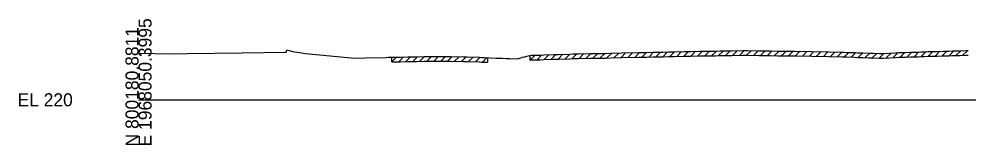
# Model space of a CAD drawing. Extents: x -119 to 6018, y -82 to 34226.
# Drawn here: x -25.7 to 178.2, y 31988.3 to 32015.3 of the extents above; entities that cross this region are included whole.
import ezdxf

# ---------------------------------------------------------------- set-up
doc = ezdxf.new("R2010")
doc.units = 0
for name, color, linetype in [('Default', 7, 'Continuous'), ('RD_GPK_XS_Cell', 7, 'Continuous'), ('RD_XS_ExGround', 7, 'Continuous'), ('RD_XS_ExPaveRet', 7, 'Continuous')]:
    doc.layers.add(name, color=color, linetype=linetype)

msp = doc.modelspace()

# ---------------------------------------------------------------- linework, layer by layer
at = {"layer": 'RD_GPK_XS_Cell'}
msp.add_line((0, 31998), (300, 31998), dxfattribs=at)
at = {"layer": 'RD_XS_ExGround'}
msp.add_lwpolyline([(0, 32008), (6.95, 32007.87), (10.52, 32007.91), (22.19, 32008.08), (31.74, 32008.2), (31.84, 32008.7), (33.05, 32008.33), (33.59, 32008.26), (34.15, 32008.21), (35.86, 32007.91), (38.17, 32007.7), (46.41, 32006.91), (48.78, 32007), (53.2, 32007.09), (53.66, 32007.11), (54.9, 32007.15), (55.85, 32007.16), (56.24, 32007.17), (57.83, 32007.2), (59.76, 32007.24), (61.35, 32007.26), (63.35, 32007.29), (65.85, 32007.32), (66.55, 32007.31), (67.02, 32007.3), (69.83, 32007.21), (70.58, 32007.19), (73.21, 32007.11), (73.69, 32007.1), (74.26, 32007.07), (75.53, 32007.01), (76.85, 32006.96), (77.22, 32006.95), (77.79, 32006.92), (78.19, 32006.91), (79, 32006.87), (79.79, 32006.85), (81.4, 32006.82), (82.11, 32007), (82.53, 32007.11), (82.98, 32007.22), (83.41, 32007.33), (84.33, 32007.55), (85.6, 32007.59), (86.38, 32007.6), (87.12, 32007.63), (89.13, 32007.71), (89.68, 32007.73), (90.22, 32007.74), (92.68, 32007.82), (93.4, 32007.84), (94.53, 32007.89), (97, 32007.93), (100.35, 32007.96), (101.41, 32007.99), (103.85, 32008.04), (107.44, 32008.11), (109.16, 32008.16), (110.53, 32008.19), (111.35, 32008.21), (112.63, 32008.24), (113.89, 32008.27), (115.08, 32008.3), (117.29, 32008.36), (117.98, 32008.38), (118.64, 32008.39), (120.64, 32008.42), (121.44, 32008.43), (122.36, 32008.44), (123.24, 32008.45), (124, 32008.46), (124.98, 32008.47), (126.14, 32008.49), (126.87, 32008.5), (127.45, 32008.51), (129.87, 32008.54), (130.86, 32008.54), (133.39, 32008.5), (134.26, 32008.49), (135.69, 32008.48), (137.33, 32008.46), (137.73, 32008.46), (139.17, 32008.45), (141.11, 32008.42), (144.68, 32008.35), (148.28, 32008.26), (151.15, 32008.2), (151.52, 32008.19), (152.14, 32008.18), (153.82, 32008.14), (154.55, 32008.1), (155.65, 32008.06), (156.91, 32008.02), (157.96, 32007.99), (159.25, 32007.94), (160.07, 32007.94), (162.66, 32008.08), (163.35, 32008.13), (164.06, 32008.14), (164.81, 32008.16), (165.87, 32008.2), (166.37, 32008.22), (167.05, 32008.24), (167.51, 32008.25), (168.17, 32008.28), (168.76, 32008.3), (169.58, 32008.33), (170.24, 32008.34), (171.55, 32008.38), (172.9, 32008.42), (174.12, 32008.45), (174.92, 32008.48), (176.42, 32008.52), (177.76, 32008.56), (178.3, 32008.57)], dxfattribs=at)
at = {"layer": 'RD_XS_ExPaveRet'}
for p, q in [((177.15, 32007.54), (178.17, 32008.57)), ((54.42, 32006.14), (55.44, 32007.16)), ((54.42, 32006.14), (54.42, 32007.14)), ((55.92, 32006.16), (56.94, 32007.18)), ((57.42, 32006.19), (58.44, 32007.21)), ((58.92, 32006.22), (59.94, 32007.24)), ((60.42, 32006.25), (61.44, 32007.27)), ((61.92, 32006.27), (62.93, 32007.29)), ((63.42, 32006.29), (64.43, 32007.3)), ((64.92, 32006.31), (65.93, 32007.32)), ((66.42, 32006.31), (67.39, 32007.29)), ((67.92, 32006.27), (68.89, 32007.24)), ((69.42, 32006.22), (70.39, 32007.19)), ((70.92, 32006.18), (71.89, 32007.15)), ((72.42, 32006.13), (73.39, 32007.11)), ((73.92, 32006.08), (74.87, 32007.04)), ((74.95, 32007.04), (74.95, 32006.04)), ((84.15, 32006.51), (85.21, 32007.58)), ((84.15, 32006.51), (84.15, 32007.51)), ((84.15, 32006.51), (84.33, 32006.55)), ((84.33, 32006.55), (85.6, 32006.59)), ((85.6, 32006.59), (86.38, 32006.6)), ((85.65, 32006.59), (86.67, 32007.61)), ((86.38, 32006.6), (87.12, 32006.63)), ((87.12, 32006.63), (89.13, 32006.71)), ((87.15, 32006.63), (88.19, 32007.67)), ((88.65, 32006.69), (89.68, 32007.73)), ((89.13, 32006.71), (89.68, 32006.73)), ((89.68, 32006.73), (90.22, 32006.74)), ((90.15, 32006.74), (91.18, 32007.77)), ((90.22, 32006.74), (92.68, 32006.82)), ((91.65, 32006.79), (92.68, 32007.82)), ((92.68, 32006.82), (93.4, 32006.84)), ((93.15, 32006.83), (94.19, 32007.87)), ((93.4, 32006.84), (94.53, 32006.89)), ((94.53, 32006.89), (97, 32006.93)), ((94.65, 32006.89), (95.67, 32007.91)), ((96.15, 32006.92), (97.17, 32007.94)), ((97, 32006.93), (100.35, 32006.96)), ((97.65, 32006.94), (98.66, 32007.95)), ((99.15, 32006.95), (100.16, 32007.96)), ((100.35, 32006.96), (101.41, 32006.99)), ((100.65, 32006.97), (101.67, 32007.99)), ((101.41, 32006.99), (103.85, 32007.04)), ((102.15, 32007), (103.17, 32008.02)), ((103.65, 32007.03), (104.67, 32008.05)), ((103.85, 32007.04), (107.44, 32007.11)), ((105.15, 32007.06), (106.17, 32008.09)), ((106.65, 32007.1), (107.67, 32008.12)), ((107.44, 32007.11), (109.16, 32007.16)), ((108.15, 32007.13), (109.17, 32008.16)), ((109.16, 32007.16), (110.53, 32007.19)), ((109.65, 32007.17), (110.67, 32008.19)), ((110.53, 32007.19), (111.35, 32007.21)), ((111.15, 32007.21), (112.17, 32008.23)), ((111.35, 32007.21), (112.63, 32007.24)), ((112.63, 32007.24), (113.89, 32007.27)), ((112.65, 32007.24), (113.67, 32008.27)), ((113.89, 32007.27), (115.08, 32007.3)), ((114.15, 32007.28), (115.17, 32008.31)), ((115.08, 32007.3), (117.29, 32007.36)), ((115.65, 32007.32), (116.68, 32008.35)), ((117.15, 32007.36), (118.17, 32008.39)), ((117.29, 32007.36), (117.98, 32007.38)), ((117.98, 32007.38), (118.64, 32007.39)), ((118.64, 32007.39), (120.64, 32007.42)), ((118.65, 32007.39), (119.66, 32008.41)), ((120.15, 32007.41), (121.16, 32008.43)), ((120.64, 32007.42), (121.44, 32007.43)), ((121.44, 32007.43), (122.36, 32007.44)), ((121.65, 32007.43), (122.66, 32008.45)), ((122.36, 32007.44), (123.24, 32007.45)), ((123.15, 32007.45), (124.16, 32008.46)), ((123.24, 32007.45), (124, 32007.46)), ((124, 32007.46), (124.98, 32007.47)), ((124.65, 32007.47), (125.66, 32008.48)), ((124.98, 32007.47), (126.14, 32007.49)), ((126.14, 32007.49), (126.87, 32007.5)), ((126.15, 32007.49), (127.16, 32008.51)), ((126.87, 32007.5), (127.45, 32007.51)), ((127.45, 32007.51), (129.87, 32007.54)), ((127.65, 32007.51), (128.66, 32008.53)), ((129.15, 32007.53), (130.15, 32008.54)), ((129.87, 32007.54), (130.86, 32007.54)), ((130.65, 32007.54), (131.64, 32008.53)), ((130.86, 32007.54), (133.39, 32007.5)), ((132.15, 32007.52), (133.13, 32008.51)), ((133.39, 32007.5), (134.26, 32007.49)), ((133.65, 32007.5), (134.64, 32008.49)), ((134.26, 32007.49), (135.69, 32007.48)), ((135.15, 32007.48), (136.14, 32008.47)), ((135.69, 32007.48), (137.33, 32007.46)), ((136.65, 32007.47), (137.64, 32008.46)), ((137.33, 32007.46), (137.73, 32007.46)), ((137.73, 32007.46), (139.17, 32007.45)), ((138.15, 32007.45), (139.14, 32008.45)), ((139.17, 32007.45), (141.11, 32007.42)), ((139.65, 32007.44), (140.64, 32008.43)), ((141.11, 32007.42), (144.68, 32007.35)), ((141.15, 32007.42), (142.13, 32008.4)), ((142.65, 32007.39), (143.63, 32008.37)), ((144.15, 32007.36), (145.13, 32008.34)), ((144.68, 32007.35), (148.28, 32007.26)), ((145.65, 32007.33), (146.62, 32008.3)), ((147.15, 32007.29), (148.12, 32008.27)), ((148.28, 32007.26), (151.15, 32007.2)), ((148.65, 32007.26), (149.63, 32008.23)), ((150.15, 32007.22), (151.13, 32008.2)), ((151.15, 32007.2), (151.52, 32007.19)), ((151.52, 32007.19), (152.14, 32007.18)), ((151.65, 32007.19), (152.63, 32008.17)), ((152.14, 32007.18), (153.82, 32007.14)), ((153.15, 32007.16), (154.12, 32008.13)), ((153.82, 32007.14), (154.55, 32007.1)), ((154.55, 32007.1), (155.65, 32007.06)), ((154.65, 32007.1), (155.61, 32008.06)), ((155.65, 32007.06), (156.91, 32007.02)), ((156.15, 32007.05), (157.12, 32008.02)), ((156.91, 32007.02), (157.96, 32006.99)), ((157.65, 32007), (158.61, 32007.96)), ((157.96, 32006.99), (159.25, 32006.94)), ((159.15, 32006.95), (160.14, 32007.94)), ((159.25, 32006.94), (160.07, 32006.94)), ((160.07, 32006.94), (162.66, 32007.08)), ((160.65, 32006.97), (161.71, 32008.03)), ((162.15, 32007.05), (163.21, 32008.12)), ((162.66, 32007.08), (163.35, 32007.13)), ((163.35, 32007.13), (164.06, 32007.14)), ((163.65, 32007.13), (164.67, 32008.16)), ((164.06, 32007.14), (164.81, 32007.16)), ((164.81, 32007.16), (165.87, 32007.2)), ((165.15, 32007.18), (166.19, 32008.21)), ((165.87, 32007.2), (166.37, 32007.22)), ((166.37, 32007.22), (167.05, 32007.24)), ((166.65, 32007.23), (167.68, 32008.26)), ((167.05, 32007.24), (167.51, 32007.25)), ((167.51, 32007.25), (168.17, 32007.28)), ((168.15, 32007.28), (169.18, 32008.31)), ((168.17, 32007.28), (168.76, 32007.3)), ((168.76, 32007.3), (169.58, 32007.33)), ((169.58, 32007.33), (170.24, 32007.34)), ((169.65, 32007.33), (170.68, 32008.36)), ((170.24, 32007.34), (171.55, 32007.38)), ((171.15, 32007.37), (172.18, 32008.4)), ((171.55, 32007.38), (172.9, 32007.42)), ((172.65, 32007.41), (173.68, 32008.44)), ((172.9, 32007.42), (174.12, 32007.45)), ((174.12, 32007.45), (174.92, 32007.48)), ((174.15, 32007.45), (175.18, 32008.48)), ((174.92, 32007.48), (176.42, 32007.52)), ((175.65, 32007.5), (176.68, 32008.53)), ((176.42, 32007.52), (177.76, 32007.56)), ((177.76, 32007.56), (178.3, 32007.57)), ((54.42, 32006.14), (54.9, 32006.15)), ((54.9, 32006.15), (55.85, 32006.16)), ((55.85, 32006.16), (56.24, 32006.17)), ((56.24, 32006.17), (57.83, 32006.2)), ((57.83, 32006.2), (59.76, 32006.24)), ((59.76, 32006.24), (61.35, 32006.26)), ((61.35, 32006.26), (63.35, 32006.29)), ((63.35, 32006.29), (65.85, 32006.32)), ((65.85, 32006.32), (66.55, 32006.31)), ((66.55, 32006.31), (67.02, 32006.3)), ((67.02, 32006.3), (69.83, 32006.21)), ((69.83, 32006.21), (70.58, 32006.19)), ((70.58, 32006.19), (73.21, 32006.11)), ((73.21, 32006.11), (73.69, 32006.1)), ((73.69, 32006.1), (74.26, 32006.07)), ((74.26, 32006.07), (74.95, 32006.04))]:
    msp.add_line(p, q, dxfattribs=at)

# ---------------------------------------------------------------- texts
at = {"layer": 'Default'}
msp.add_text('-', height=0.0001, dxfattribs=at).set_placement((0, 31998))
at = {"layer": 'RD_GPK_XS_Cell'}
for s, p in [('E 1968050.3995', (2.8, 31988)), ('N 800180.8811', (0, 31988))]:
    msp.add_text(s, height=2.8, rotation=90, dxfattribs=at).set_placement(p)
msp.add_text('EL 220', height=2.8, dxfattribs=at).set_placement((-26, 31996.6))

doc.saveas('drawing.dxf')
